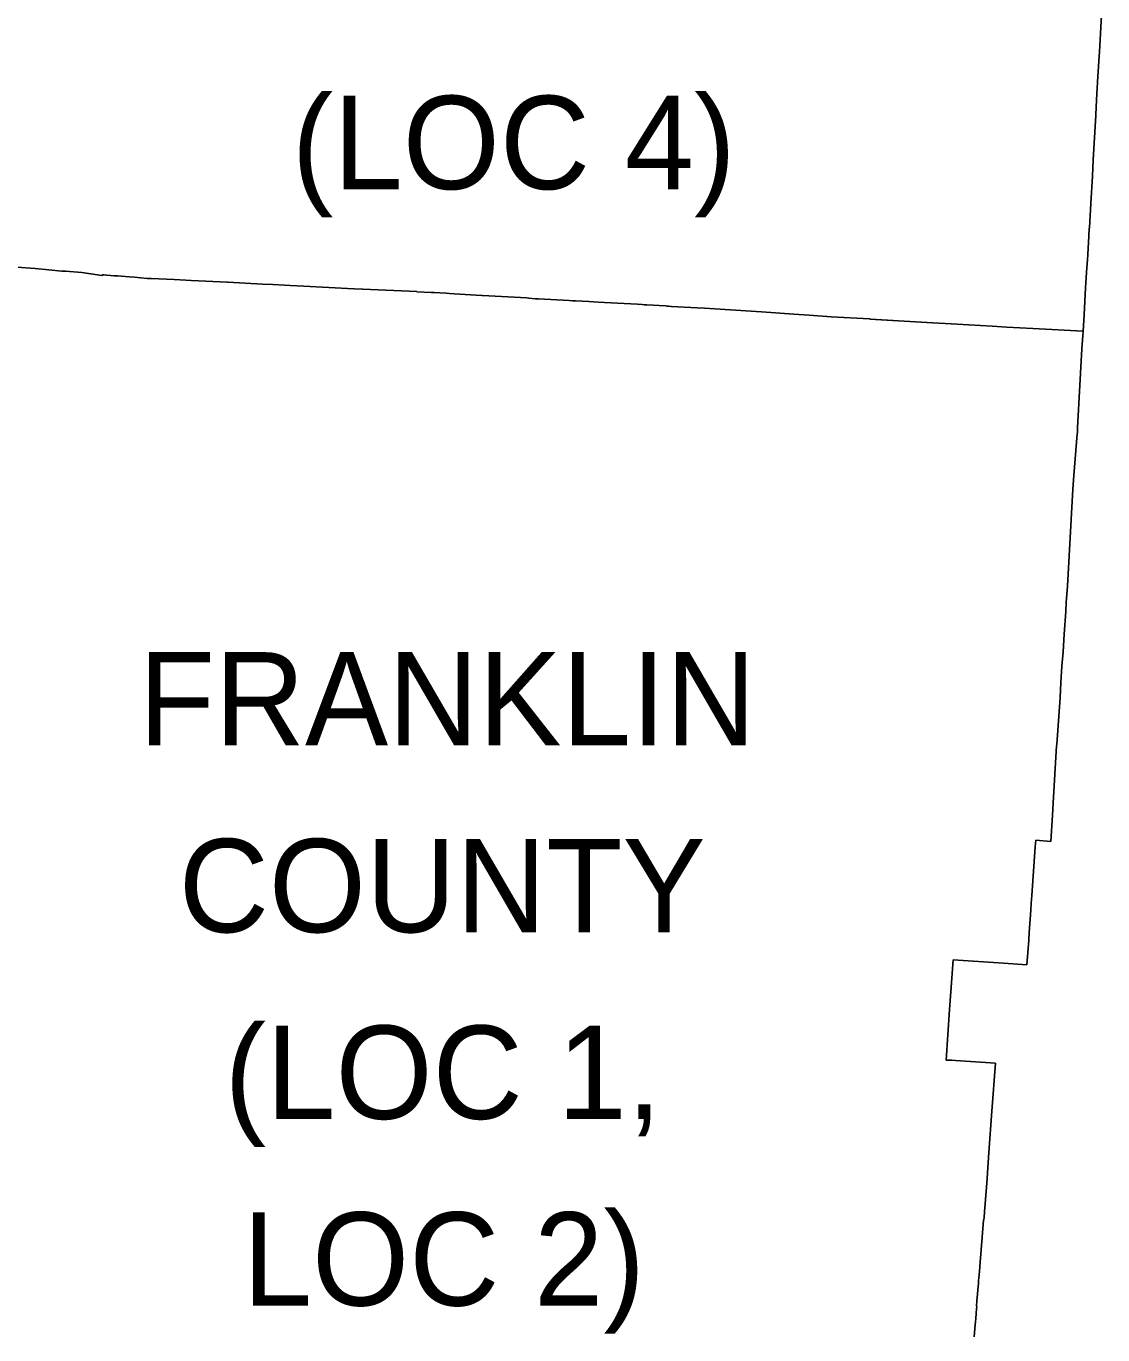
# Model space of a CAD drawing. Extents: x 0 to 34, y 0 to 22.
# Drawn here: x 5.53 to 7.062, y 16.496 to 18.358 of the extents above; entities that cross this region are included whole.
import ezdxf

# ---------------------------------------------------------------- set-up
doc = ezdxf.new("R2010")
doc.units = 0
doc.layers.add('GM_X_County', color=7, linetype='Continuous')
doc.layers.add('SH_Data', color=7, linetype='Continuous')

msp = doc.modelspace()

# ---------------------------------------------------------------- linework, layer by layer
at = {"layer": 'GM_X_County'}
for p, q in [((7.0616, 18.4073), (7.0567, 18.3217)), ((7.0567, 18.3217), (7.0564, 18.3154)), ((7.0564, 18.3154), (7.0546, 18.2864)), ((7.0546, 18.2864), (7.0532, 18.2617)), ((7.0526, 18.2525), (7.0516, 18.2323)), ((7.0532, 18.2617), (7.0526, 18.2525)), ((7.0514, 18.2309), (7.048, 18.1678)), ((7.0516, 18.2323), (7.0514, 18.2309)), ((7.048, 18.1678), (7.0467, 18.1445)), ((7.0467, 18.1445), (7.0445, 18.1055)), ((7.0445, 18.1055), (7.0424, 18.0712)), ((7.0423, 18.0701), (7.0416, 18.0593)), ((7.0424, 18.0712), (7.0423, 18.0701)), ((7.0416, 18.0593), (7.04, 18.033)), ((7.0396, 18.0257), (7.0389, 18.0147)), ((7.04, 18.033), (7.0396, 18.0257)), ((5.5424, 18.0131), (5.5163, 18.0153)), ((5.5619, 18.0115), (5.5424, 18.0131)), ((5.5802, 18.0096), (5.5619, 18.0115)), ((5.5856, 18.0094), (5.5802, 18.0096)), ((5.6089, 18.0074), (5.5856, 18.0094)), ((5.6372, 18.0034), (5.6089, 18.0074)), ((7.0389, 18.0147), (7.0371, 17.9858)), ((5.6384, 18.004), (5.6372, 18.0034)), ((5.6396, 18.0042), (5.6384, 18.004)), ((5.6407, 18.004), (5.6396, 18.0042)), ((5.6445, 18.0038), (5.6407, 18.004)), ((5.6548, 18.003), (5.6445, 18.0038)), ((5.6597, 18.0026), (5.6548, 18.003)), ((5.6652, 18.0022), (5.6597, 18.0026)), ((5.6763, 18.0014), (5.6652, 18.0022)), ((5.6839, 18.0007), (5.6763, 18.0014)), ((5.7019, 17.999), (5.6839, 18.0007)), ((5.7074, 17.999), (5.7019, 17.999)), ((5.7401, 17.9974), (5.7074, 17.999)), ((5.7567, 17.9967), (5.7401, 17.9974)), ((5.7644, 17.9963), (5.7567, 17.9967)), ((5.7854, 17.995), (5.7644, 17.9963)), ((5.8154, 17.9938), (5.7854, 17.995)), ((5.8163, 17.9938), (5.8154, 17.9938)), ((5.8659, 17.991), (5.8163, 17.9938)), ((5.8807, 17.9904), (5.8659, 17.991)), ((5.8972, 17.9893), (5.8807, 17.9904)), ((5.905, 17.9889), (5.8972, 17.9893)), ((5.9246, 17.9879), (5.905, 17.9889)), ((5.9959, 17.9842), (5.9246, 17.9879)), ((7.0371, 17.9858), (7.0349, 17.9475)), ((5.9963, 17.9842), (5.9959, 17.9842)), ((6.0083, 17.9839), (5.9963, 17.9842)), ((6.0088, 17.9839), (6.0083, 17.9839)), ((6.0852, 17.9803), (6.0088, 17.9839)), ((6.0856, 17.9802), (6.0852, 17.9803)), ((6.1057, 17.9791), (6.0856, 17.9802)), ((6.1091, 17.979), (6.1057, 17.9791)), ((6.1103, 17.979), (6.1091, 17.979)), ((6.1183, 17.9786), (6.1103, 17.979)), ((6.1272, 17.9781), (6.1183, 17.9786)), ((6.1318, 17.9778), (6.1272, 17.9781)), ((6.1385, 17.9774), (6.1318, 17.9778)), ((6.1781, 17.9749), (6.1385, 17.9774)), ((6.1788, 17.9748), (6.1781, 17.9749)), ((6.2418, 17.9713), (6.1788, 17.9748)), ((6.2449, 17.971), (6.2418, 17.9713)), ((6.2542, 17.9703), (6.2449, 17.971)), ((6.2587, 17.9701), (6.2542, 17.9703)), ((6.3021, 17.9677), (6.2587, 17.9701)), ((6.3068, 17.9674), (6.3021, 17.9677)), ((6.311, 17.9671), (6.3068, 17.9674)), ((6.3301, 17.9661), (6.311, 17.9671)), ((6.3434, 17.9654), (6.3301, 17.9661)), ((6.3711, 17.9639), (6.3434, 17.9654)), ((6.3992, 17.9623), (6.3711, 17.9639)), ((6.4062, 17.9619), (6.3992, 17.9623)), ((6.4087, 17.9617), (6.4062, 17.9619)), ((6.4128, 17.9615), (6.4087, 17.9617)), ((6.4392, 17.9599), (6.4128, 17.9615)), ((6.4415, 17.9598), (6.4392, 17.9599)), ((6.4436, 17.9596), (6.4415, 17.9598)), ((6.4475, 17.9594), (6.4436, 17.9596)), ((6.448, 17.9594), (6.4475, 17.9594)), ((6.4845, 17.9573), (6.448, 17.9594)), ((6.4947, 17.9567), (6.4845, 17.9573)), ((6.5094, 17.9558), (6.4947, 17.9567)), ((6.5757, 17.9514), (6.5094, 17.9558)), ((6.6221, 17.9482), (6.5757, 17.9514)), ((6.6435, 17.9468), (6.6221, 17.9482)), ((6.6751, 17.9446), (6.6435, 17.9468)), ((6.7294, 17.9414), (6.6751, 17.9446)), ((6.7301, 17.9413), (6.7294, 17.9414)), ((6.8113, 17.9366), (6.7301, 17.9413)), ((6.7301, 17.9413), (6.7308, 17.9413)), ((6.7308, 17.9413), (6.8113, 17.9366)), ((6.8541, 17.9341), (6.8113, 17.9366)), ((6.9041, 17.9312), (6.8541, 17.9341)), ((6.9251, 17.93), (6.9041, 17.9312)), ((6.9618, 17.9277), (6.9251, 17.93)), ((7.0349, 17.9475), (7.0335, 17.924)), ((7.0335, 17.924), (6.9618, 17.9277)), ((7.0331, 17.9175), (7.0319, 17.8989)), ((7.0335, 17.924), (7.0331, 17.9175)), ((7.0319, 17.8989), (7.0257, 17.7864)), ((7.0256, 17.7858), (7.0253, 17.7789)), ((7.0257, 17.7864), (7.0256, 17.7858)), ((7.0251, 17.7781), (7.0203, 17.7186)), ((7.0252, 17.7783), (7.0251, 17.7781)), ((7.0253, 17.7789), (7.0252, 17.7783)), ((7.0203, 17.7186), (7.0191, 17.6994)), ((7.0191, 17.6994), (7.0111, 17.5612)), ((7.0111, 17.5612), (7.0095, 17.5381)), ((7.0087, 17.5252), (7.0067, 17.4932)), ((7.0095, 17.5381), (7.0087, 17.5252)), ((7.0067, 17.4932), (7.0049, 17.4678)), ((7.0049, 17.4678), (7.0034, 17.4475)), ((7.0034, 17.4475), (7.0019, 17.424)), ((7.0019, 17.424), (7.0007, 17.4027)), ((7.0007, 17.4027), (6.9959, 17.3361)), ((6.9958, 17.3341), (6.9911, 17.2528)), ((6.9959, 17.3361), (6.9958, 17.3341)), ((6.9911, 17.2528), (6.9899, 17.2349)), ((6.9899, 17.2349), (6.9874, 17.1979)), ((6.9653, 17.1902), (6.9605, 17.1213)), ((6.966, 17.1998), (6.9653, 17.1902)), ((6.9874, 17.1979), (6.966, 17.1998)), ((6.9605, 17.1213), (6.9597, 17.1097)), ((6.959, 17.1002), (6.9568, 17.0686)), ((6.9597, 17.1097), (6.959, 17.1002)), ((6.9561, 17.0577), (6.9536, 17.0224)), ((6.9568, 17.0686), (6.9561, 17.0577)), ((6.8484, 17.0296), (6.8453, 16.9843)), ((6.92, 17.0247), (6.8484, 17.0296)), ((6.9536, 17.0224), (6.92, 17.0247)), ((6.8453, 16.9843), (6.8436, 16.9588)), ((6.8436, 16.9588), (6.8386, 16.8869)), ((6.8386, 16.8869), (6.8463, 16.8867)), ((6.8463, 16.8867), (6.8519, 16.8864)), ((6.8519, 16.8864), (6.9086, 16.8825)), ((6.9086, 16.8825), (6.9036, 16.8142)), ((6.9036, 16.8142), (6.8992, 16.7553)), ((6.8992, 16.7553), (6.8968, 16.7191)), ((6.8959, 16.7064), (6.8946, 16.6887)), ((6.8968, 16.7184), (6.8959, 16.7064)), ((6.8968, 16.7191), (6.8968, 16.7184)), ((6.8946, 16.6887), (6.8933, 16.6712)), ((6.8933, 16.6712), (6.8927, 16.663)), ((6.8919, 16.6592), (6.8899, 16.6352)), ((6.8924, 16.6604), (6.8919, 16.6592)), ((6.8927, 16.663), (6.8924, 16.6604)), ((6.8899, 16.6352), (6.887, 16.5993)), ((6.887, 16.5993), (6.8859, 16.5865)), ((6.8848, 16.5733), (6.8846, 16.5695)), ((6.8851, 16.5774), (6.8848, 16.5733)), ((6.8856, 16.5814), (6.8851, 16.5774)), ((6.8859, 16.5865), (6.8856, 16.5814)), ((6.8846, 16.5695), (6.8823, 16.5443)), ((6.8819, 16.5335), (6.8807, 16.5192)), ((6.8821, 16.5354), (6.8819, 16.5335)), ((6.8823, 16.5443), (6.882, 16.5371)), ((6.882, 16.5371), (6.8821, 16.5365)), ((6.8821, 16.5365), (6.8821, 16.5354)), ((6.8807, 16.5192), (6.8803, 16.5148)), ((6.8795, 16.5053), (6.8785, 16.4932)), ((6.88, 16.5104), (6.8795, 16.5053)), ((6.8803, 16.5148), (6.88, 16.5104))]:
    msp.add_line(p, q, dxfattribs=at)

# ---------------------------------------------------------------- texts
at = {"layer": 'SH_Data'}
for s, p in [('(LOC 4)', (5.9075, 18.1261)), ('FRANKLIN', (5.6895, 17.3346)), ('COUNTY', (5.7466, 17.0689)), ('(LOC 1,', (5.8118, 16.8033)), ('LOC 2)', (5.8376, 16.5377))]:
    msp.add_text(s, height=0.13282, dxfattribs=at).set_placement(p)

doc.saveas('drawing.dxf')
